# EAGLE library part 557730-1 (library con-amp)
AMP connector
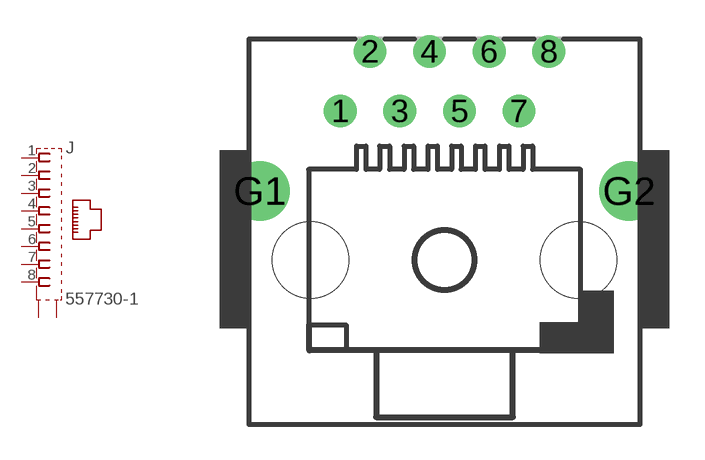
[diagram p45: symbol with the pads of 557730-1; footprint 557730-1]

Designator prefix J

## 557730-1 (MF: TYCO ELECTRONICS; MPN: 5557730-1; OC_FARNELL: 1704449; OC_NEWARK: 42K9935)  [557730-1]
1  1  pas
2  2  pas
3  3  pas
4  4  pas
5  5  pas
6  6  pas
7  7  pas
8  8  pas
G1  S2  pas
G2  S1  pas

## Footprint 557730-1 (pad centres in mm)
Modular Jack Keyed - Shielded with Panel Stops
drill 0.889 round: 1 -4.445,6.35; 2 -3.175,8.89; 3 -1.905,6.35; 4 -0.635,8.89; 5 0.635,6.35; 6 1.905,8.89; 7 3.175,6.35; 8 4.445,8.89
drill 1.524 pad 2.54 round: G1 -7.874,2.946; G2 7.874,2.946
hole 3.251 at -5.715,0
hole 3.251 at 5.715,0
